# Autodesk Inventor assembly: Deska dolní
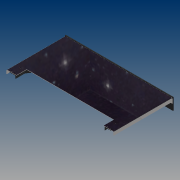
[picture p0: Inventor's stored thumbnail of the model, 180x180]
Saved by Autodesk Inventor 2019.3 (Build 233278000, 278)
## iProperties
Created: 2019-02
Part Number: Deska dolní
Material: Všeobecné
Document SubType Name: Assembly
Designer: B-hon
Author: B-hon
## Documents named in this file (8)
- C:\Users\B-hon\OneDrive\Plocha\Bakalářka22\Deska dolní\Deska dolní.iam
- C:\Users\B-hon\OneDrive\Plocha\Bakalářka22\Deska dolní\Plech deskyd.ipt
- C:\Users\B-hon\OneDrive\Plocha\Bakalářka22\Deska dolní\Výztuha1d.ipt
- C:\Users\B-hon\OneDrive\Plocha\Bakalářka22\Deska dolní\Výztuha2d.ipt
- C:\Users\B-hon\OneDrive\Plocha\Bakalářka22\Deska dolní\Lišta1d.ipt
- C:\Users\B-hon\OneDrive\Plocha\Bakalářka22\Rolna leva.iam
- C:\Users\B-hon\OneDrive\Plocha\Bakalářka22\Rolna prava.iam
- C:\Users\B-hon\OneDrive\Documents\Inventor\Content Center Files\R2019\cs-CZ\DIN 7991(2)\DIN 7991 - M5x8.ipt
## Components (14 placed, 7 different names)
1. Plech deskyd:1 — Vložit:1, Vložit:2, Vložit:3, Vložit:4, Vložit:5, Vložit:6
2. Výztuha1d:1 — Vložit:3, Vložit:4
3. Výztuha2d:1 — Vložit:1, Vložit:2
4. Lišta1d:1 — Vložit:5, Vložit:6, Vložit:7, Vložit:8, Vložit:9, Vložit:10
5. Rolna leva:1 [sub-assembly] — Vložit:7, Vložit:10
6. Rolna prava:1 [sub-assembly] — Vložit:8, Vložit:9
7. DIN 7991 M5x8:5
8. DIN 7991 M5x8:6
9. DIN 7991 M5x8:7
10. DIN 7991 M5x8:8
11. DIN 7991 M5x8:1
12. DIN 7991 M5x8:2
13. DIN 7991 M5x8:3
14. DIN 7991 M5x8:4
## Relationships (10: Insert 10)
- Vložit:1 [Insert]: Plech deskyd:1 ↔ Výztuha2d:1
- Vložit:2 [Insert]: Plech deskyd:1 ↔ Výztuha2d:1
- Vložit:3 [Insert]: Plech deskyd:1 ↔ Výztuha1d:1
- Vložit:4 [Insert]: Plech deskyd:1 ↔ Výztuha1d:1
- Vložit:5 [Insert]: Plech deskyd:1 ↔ Lišta1d:1
- Vložit:6 [Insert]: Plech deskyd:1 ↔ Lišta1d:1
- Vložit:7 [Insert]: Lišta1d:1 ↔ Rolna leva:1
- Vložit:8 [Insert]: Lišta1d:1 ↔ Rolna prava:1
- Vložit:9 [Insert]: Lišta1d:1 ↔ Rolna prava:1
- Vložit:10 [Insert]: Lišta1d:1 ↔ Rolna leva:1
